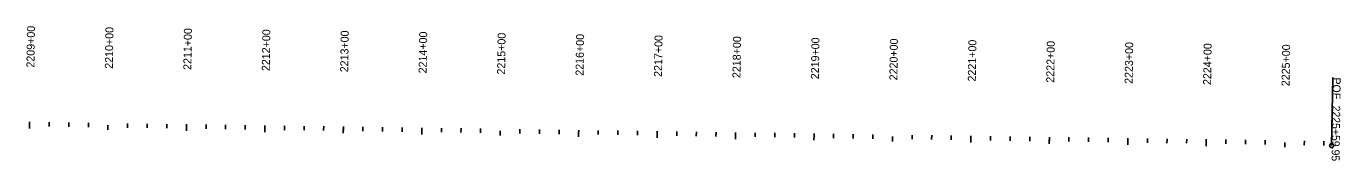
# Model space of a CAD drawing. Extents: x 14295116 to 14303545, y 8637313 to 8653417.
# Drawn here: x 14301407 to 14303082, y 8637519 to 8637691 of the extents above; entities that cross this region are included whole.
import ezdxf

# ---------------------------------------------------------------- set-up
doc = ezdxf.new("R2010")
doc.units = 0
for name, color, linetype in [('CulvertProposed', 7, 'Continuous'), ('Draft_DNC', 7, 'Continuous'), ('G Prop 6 Valve (B1) CELL', 7, 'Continuous')]:
    doc.layers.add(name, color=color, linetype=linetype)

msp = doc.modelspace()

# ---------------------------------------------------------------- linework, layer by layer
at = {"layer": 'CulvertProposed'}
msp.add_line((14303070.4, 8637538.1), (14303071.7, 8637625.1), dxfattribs=at)
msp.add_circle((14303070.4, 8637538.1), 2.67, dxfattribs=at)
at = {"layer": 'Draft_DNC'}
for p, q in [((14301410.7, 8637565.8), (14301410.6, 8637559.7)), ((14301435.7, 8637562.4), (14301435.8, 8637567.9)), ((14301460.7, 8637562), (14301460.8, 8637567.5)), ((14301485.7, 8637561.7), (14301485.7, 8637567.1)), ((14301510.7, 8637564.3), (14301510.6, 8637558.2)), ((14301535.7, 8637560.9), (14301535.7, 8637566.4)), ((14301560.7, 8637560.5), (14301560.7, 8637566)), ((14301585.7, 8637560.2), (14301585.7, 8637565.6)), ((14301610.7, 8637562.9), (14301610.6, 8637556.7)), ((14301635.7, 8637559.4), (14301635.7, 8637564.9)), ((14301660.6, 8637559.1), (14301660.7, 8637564.5)), ((14301685.6, 8637558.7), (14301685.7, 8637564.1)), ((14301710.7, 8637561.4), (14301710.6, 8637555.3)), ((14301735.6, 8637557.9), (14301735.7, 8637563.4)), ((14301760.6, 8637557.6), (14301760.7, 8637563)), ((14301785.6, 8637557.2), (14301785.7, 8637562.7)), ((14301810.7, 8637559.9), (14301810.6, 8637553.8)), ((14301835.6, 8637556.5), (14301835.7, 8637561.9)), ((14301860.6, 8637556.1), (14301860.7, 8637561.5)), ((14301885.6, 8637555.7), (14301885.7, 8637561.2)), ((14301910.7, 8637558.4), (14301910.6, 8637552.3)), ((14301935.6, 8637555), (14301935.7, 8637560.4)), ((14301960.6, 8637554.6), (14301960.7, 8637560.1)), ((14301985.6, 8637554.2), (14301985.7, 8637559.7)), ((14302010.7, 8637556.9), (14302010.6, 8637550.8)), ((14302035.6, 8637553.5), (14302035.7, 8637558.9)), ((14302060.6, 8637553.1), (14302060.7, 8637558.6)), ((14302085.6, 8637552.7), (14302085.7, 8637558.2)), ((14302110.6, 8637555.4), (14302110.6, 8637549.3)), ((14302135.6, 8637552), (14302135.7, 8637557.5)), ((14302160.6, 8637551.6), (14302160.7, 8637557.1)), ((14302185.6, 8637551.3), (14302185.7, 8637556.7)), ((14302210.6, 8637554), (14302210.5, 8637547.8)), ((14302235.6, 8637550.5), (14302235.7, 8637556)), ((14302260.6, 8637550.1), (14302260.7, 8637555.6)), ((14302285.6, 8637549.8), (14302285.7, 8637555.2)), ((14302335.6, 8637549), (14302335.7, 8637554.5)), ((14302360.6, 8637548.7), (14302360.7, 8637554.1)), ((14302385.6, 8637548.3), (14302385.6, 8637553.8)), ((14302310.6, 8637552.5), (14302310.5, 8637546.3)), ((14302410.6, 8637551), (14302410.5, 8637544.9)), ((14302435.6, 8637547.6), (14302435.6, 8637553)), ((14302460.6, 8637547.2), (14302460.6, 8637552.6)), ((14302485.6, 8637546.8), (14302485.6, 8637552.3)), ((14302510.6, 8637549.5), (14302510.5, 8637543.4)), ((14302535.6, 8637546.1), (14302535.6, 8637551.5)), ((14302560.5, 8637545.7), (14302560.6, 8637551.2)), ((14302585.5, 8637545.3), (14302585.6, 8637550.8)), ((14302610.6, 8637548), (14302610.5, 8637541.9)), ((14302635.5, 8637544.6), (14302635.6, 8637550)), ((14302660.5, 8637544.2), (14302660.6, 8637549.7)), ((14302685.5, 8637543.8), (14302685.6, 8637549.3)), ((14302710.6, 8637546.5), (14302710.5, 8637540.4)), ((14302735.5, 8637543.1), (14302735.6, 8637548.6)), ((14302760.5, 8637542.7), (14302760.6, 8637548.2)), ((14302785.5, 8637542.4), (14302785.6, 8637547.8)), ((14302810.6, 8637545), (14302810.5, 8637538.9)), ((14302835.5, 8637541.6), (14302835.6, 8637547.1)), ((14302860.5, 8637541.2), (14302860.6, 8637546.7)), ((14302885.5, 8637540.9), (14302885.6, 8637546.3)), ((14302910.6, 8637543.6), (14302910.5, 8637537.4)), ((14302935.5, 8637540.1), (14302935.6, 8637545.6)), ((14302960.5, 8637539.8), (14302960.6, 8637545.2)), ((14302985.5, 8637539.4), (14302985.6, 8637544.8)), ((14303010.5, 8637542.1), (14303010.5, 8637536)), ((14303035.5, 8637538.6), (14303035.6, 8637544.1)), ((14303060.5, 8637538.3), (14303060.6, 8637543.7))]:
    msp.add_line(p, q, dxfattribs=at)
at = {"layer": 'G Prop 6 Valve (B1) CELL'}
for p, q in [((14301410.7, 8637562.8), (14301410.8, 8637568.2)), ((14301510.7, 8637564.3), (14301510.6, 8637558.2)), ((14301610.7, 8637559.8), (14301610.7, 8637565.3)), ((14301710.6, 8637558.3), (14301710.7, 8637563.8)), ((14301810.6, 8637556.8), (14301810.7, 8637562.3)), ((14301910.6, 8637555.3), (14301910.7, 8637560.8)), ((14302010.7, 8637556.9), (14302010.6, 8637550.8)), ((14302110.6, 8637552.4), (14302110.7, 8637557.8)), ((14302210.6, 8637550.9), (14302210.7, 8637556.4)), ((14302310.6, 8637549.4), (14302310.7, 8637554.9)), ((14302410.6, 8637547.9), (14302410.6, 8637553.4)), ((14302510.6, 8637549.5), (14302510.5, 8637543.4)), ((14302610.5, 8637545), (14302610.6, 8637550.4)), ((14302710.5, 8637543.5), (14302710.6, 8637548.9)), ((14302810.5, 8637542), (14302810.6, 8637547.4)), ((14302910.5, 8637540.5), (14302910.6, 8637546)), ((14303010.5, 8637542.1), (14303010.5, 8637536))]:
    msp.add_line(p, q, dxfattribs=at)

# ---------------------------------------------------------------- texts
at = {"layer": 'CulvertProposed'}
for s, p in [('POE ', (14303071.9, 8637625.1)), ('2225+59.95', (14303071.4, 8637589.2))]:
    msp.add_text(s, height=10.02, rotation=269.1493, dxfattribs=at).set_placement(p)
at = {"layer": 'Draft_DNC'}
for s, p in [('2209+00', (14301416.9, 8637637.7)), ('2210+00', (14301516.9, 8637636.2)), ('2211+00', (14301616.9, 8637634.7)), ('2212+00', (14301716.9, 8637633.2)), ('2213+00', (14301816.8, 8637631.7)), ('2214+00', (14301916.8, 8637630.3)), ('2215+00', (14302016.8, 8637628.8)), ('2216+00', (14302116.8, 8637627.3)), ('2217+00', (14302216.8, 8637625.8)), ('2218+00', (14302316.8, 8637624.3)), ('2219+00', (14302416.8, 8637622.8)), ('2220+00', (14302516.8, 8637621.4)), ('2221+00', (14302616.8, 8637619.9)), ('2222+00', (14302716.7, 8637618.4)), ('2223+00', (14302816.7, 8637616.9)), ('2224+00', (14302916.7, 8637615.4)), ('2225+00', (14303016.7, 8637613.9))]:
    msp.add_text(s, height=10.2, rotation=89.1493, dxfattribs=at).set_placement(p)
at = {"layer": 'G Prop 6 Valve (B1) CELL'}
for s, p in [('2210+00', (14301516.9, 8637636.2)), ('2215+00', (14302016.8, 8637628.8)), ('2220+00', (14302516.8, 8637621.4)), ('2225+00', (14303016.7, 8637613.9))]:
    msp.add_text(s, height=10.2, rotation=89.1493, dxfattribs=at).set_placement(p)

doc.saveas('drawing.dxf')
